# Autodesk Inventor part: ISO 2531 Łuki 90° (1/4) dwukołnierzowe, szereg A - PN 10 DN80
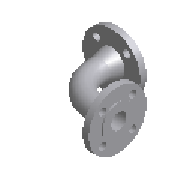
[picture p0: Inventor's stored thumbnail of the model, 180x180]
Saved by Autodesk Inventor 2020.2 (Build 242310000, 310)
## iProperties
Manager: www.cadconsulting.pl
Company: Fabian Stasiak CAD Consulting
NAME: PIPING: ISO 2531 90 Deg Double Flanged Bend - PN 10
DATA: <meta><inlinegroups number="0" deflen="0"></inlinegroups><connections number="2"></connections><angles><a>1.5707963267949</a></angles></meta>
IsCustomPart: 0
Created: 2014-02
Part Number: ISO 2531 Łuki 90° (1/4) dwukołnierzowe, szereg A - PN 10 DN80
Material: Żeliwo sferoidalne
Description: Rury, łączniki, akcesoria z żeliwa sferoidalnego i ich złącza do zastosowań w instalacjach wodnych lub gazowych - Łuki 90° (1/4) dwukołnierzowe - PN 10
Document SubType Name: Modeling
Standard: ISO 2531
Designer: F.Stasiak
Standard Revision: Fifth edition 1998-08-15
Standards Organization: ISO
Language: pl-PL
Size Designation: DN80
Categories: <MemberInstance><Categories><Category DisplayName="Rury cienko- i grubościenne" InternalName="4347fa0f-2144-441d-94cd-e3e15c92b736" Mnemonic="TUBEANDPIPE"><Cate
Density: 7.15 g/cm^3
Appearance: Ciemnoszary
Catalog Web Link: www.expertbooks.pl
Author: F.Stasiak
Subject: Zbiór ćwiczeń. Autodesk Inventor 2020. Kurs Professional
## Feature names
1. Revolution1
2. Sweep1
3. Revolution2
4. Extrusion1
5. Circular Pattern1
6. Extrusion2
7. Circular Pattern2
## Parameters: L2 = 19 mm, f1 = 3 mm, d11 = 132 mm, e = 7 mm, L = 165 mm, C7 = 19 mm, d2 = 7 mm, d3 = 132 mm, d4 = 3 mm, d5 = 15 deg, d15 = 90 deg, d8 = 165 mm, d9 = 7 mm, d10 = 3 mm, d13 = 132 mm, d18 = 7 mm, d19 = 0, d27 = 90 deg, d21 = 16 mm, d22 = 0, d24 = 360 deg, d26 = 16 mm, d28 = 0, d30 = 360 deg, d31 = 19 mm, d32 = 19 mm, d34 = 19 mm, d35 = 22.5 deg, d36 = 22.5 deg, d37 = 19 mm, d48 = 0, Size_Designation = 12.345 mm
